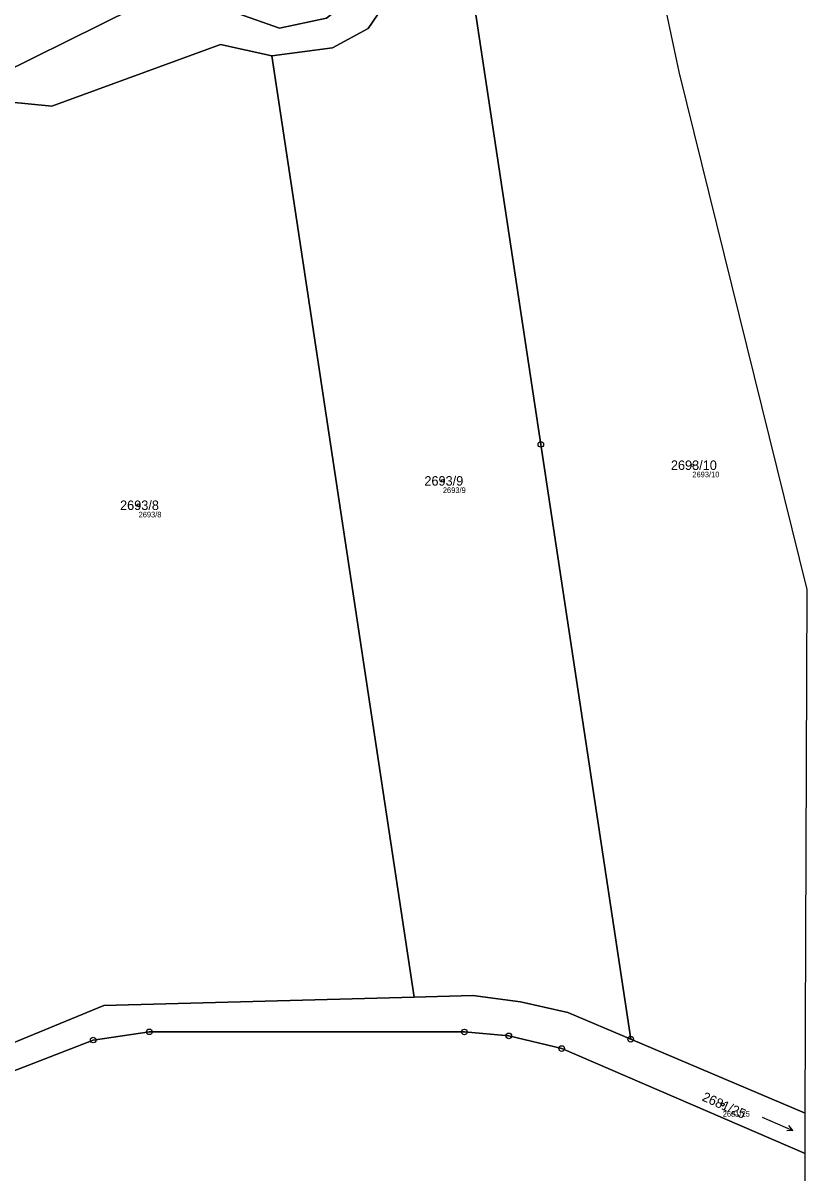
# Model space of a CAD drawing. Extents: x -758777 to -757896, y -1175225 to -1174486.
# Drawn here: x -758036.1 to -757895.9, y -1174952.5 to -1174746.8 of the extents above; entities that cross this region are included whole.
import ezdxf

# ---------------------------------------------------------------- set-up
doc = ezdxf.new("R2010")
doc.units = 0
for name, color, linetype in [('Definiční body', 7, 'Continuous'), ('Hranice parcel', 7, 'Continuous'), ('Parcelní čísla', 7, 'Continuous'), ('Polygon parcely', 7, 'Continuous'), ('Značky bodu BP', 7, 'Continuous'), ('Značky kultur', 7, 'Continuous')]:
    doc.layers.add(name, color=color, linetype=linetype)

msp = doc.modelspace()

# ---------------------------------------------------------------- linework, layer by layer
at = {"layer": 'Definiční body'}
for centre in [(-757916.44, -1174825.87), (-757961.06, -1174828.68), (-758015.47, -1174833.04), (-757911, -1174940.28)]:
    msp.add_circle(centre, 0.25, dxfattribs=at)
at = {"layer": 'Hranice parcel'}
for p, q in [((-757966.21, -1174921.06), (-757991.64, -1174752.6)), ((-757927.46, -1174928.58), (-757896.24, -1174941.82))]:
    msp.add_line(p, q, dxfattribs=at)
for points in [[(-757934.61, -1174680.85), (-757964.85, -1174709.42), (-757976.05, -1174741.17), (-757981.89, -1174745.86), (-757990.29, -1174747.68), (-757997.69, -1174745.08), (-758004.14, -1174738), (-758040.32, -1174755.99), (-758089.84, -1174768.68), (-758142.71, -1174770.26), (-758184.87, -1174772.83)], [(-757991.64, -1174752.6), (-757980.81, -1174751.2), (-757974.41, -1174747.76), (-757967.73, -1174737.89), (-757961.29, -1174718.5), (-757959.61, -1174715.65)], [(-757959.61, -1174715.65), (-757943.53, -1174822.15), (-757927.46, -1174928.58)], [(-757991.64, -1174752.6), (-758000.82, -1174750.62), (-758030.99, -1174761.66), (-758038.84, -1174760.87), (-758056.09, -1174765.35)], [(-757896.26, -1174949.04), (-757939.8, -1174930.25), (-757949.26, -1174927.98), (-757957.21, -1174927.28), (-758013.54, -1174927.25), (-758023.59, -1174928.73), (-758047.8, -1174938.11), (-758063.96, -1174936.81), (-758089.79, -1174931.96), (-758110.46, -1174923.41), (-758137.06, -1174918.45)], [(-758040.03, -1174930.09), (-758021.7, -1174922.52), (-757966.21, -1174921.06)], [(-757966.21, -1174921.06), (-757955.71, -1174920.78), (-757947.16, -1174921.89), (-757938.71, -1174923.81), (-757927.46, -1174928.58)]]:
    msp.add_lwpolyline(points, dxfattribs=at)
at = {"layer": 'Polygon parcely'}
msp.add_line((-757896.26, -1174949.04), (-757896.24, -1174941.82), dxfattribs=at)
for points in [[(-758267.96, -1174782.93), (-758224.96, -1174775.27), (-758184.87, -1174772.83), (-758142.71, -1174770.26), (-758089.84, -1174768.68), (-758040.32, -1174755.99), (-758004.14, -1174738), (-757997.69, -1174745.08), (-757990.29, -1174747.68), (-757981.89, -1174745.86), (-757976.05, -1174741.17), (-757964.85, -1174709.42), (-757934.61, -1174680.85)], [(-757932.38, -1174691.39), (-757939.6, -1174695.85), (-757955.61, -1174708.87), (-757959.61, -1174715.65), (-757943.53, -1174822.15), (-757927.46, -1174928.58), (-757896.24, -1174941.82)], [(-757896.24, -1174941.82), (-757895.94, -1174848.13), (-757918.79, -1174755.48), (-757932.38, -1174691.39)], [(-758004.14, -1174738), (-758040.32, -1174755.99), (-758089.84, -1174768.68), (-758142.71, -1174770.26), (-758184.87, -1174772.83), (-758184.92, -1174776.46), (-758157.99, -1174775.16), (-758156.63, -1174775.13), (-758141.37, -1174774.78), (-758125.97, -1174774.42), (-758112.36, -1174774.1), (-758087.64, -1174773.53), (-758083.84, -1174772.54), (-758056.09, -1174765.35), (-758038.84, -1174760.87), (-758030.99, -1174761.66), (-758000.82, -1174750.62), (-757991.64, -1174752.6), (-757980.81, -1174751.2), (-757974.41, -1174747.76), (-757967.73, -1174737.89)], [(-757981.89, -1174745.86), (-757990.29, -1174747.68), (-757997.69, -1174745.08)], [(-757896.24, -1174941.82), (-757927.46, -1174928.58), (-757938.71, -1174923.81), (-757947.16, -1174921.89), (-757955.71, -1174920.78), (-757966.21, -1174921.06), (-758021.7, -1174922.52), (-758040.03, -1174930.09)], [(-758047.8, -1174938.11), (-758023.59, -1174928.73), (-758013.54, -1174927.25), (-757957.21, -1174927.28), (-757949.26, -1174927.98), (-757939.8, -1174930.25), (-757896.26, -1174949.04)], [(-757896.26, -1174949.04), (-757939.8, -1174930.25), (-757949.26, -1174927.98), (-757957.21, -1174927.28), (-758013.54, -1174927.25), (-758023.59, -1174928.73), (-758047.8, -1174938.11)], [(-758264.85, -1175093.62), (-758230.82, -1175080.28), (-758125.25, -1175071.01), (-757896.3, -1174959.75), (-757896.26, -1174949.04)]]:
    msp.add_lwpolyline(points, dxfattribs=at)
for points in [[(-757927.46, -1174928.58), (-757943.53, -1174822.15), (-757959.61, -1174715.65), (-757961.29, -1174718.5), (-757967.73, -1174737.89), (-757974.41, -1174747.76), (-757980.81, -1174751.2), (-757991.64, -1174752.6), (-757966.21, -1174921.06), (-757955.71, -1174920.78), (-757947.16, -1174921.89), (-757938.71, -1174923.81)], [(-758000.82, -1174750.62), (-758030.99, -1174761.66), (-758038.84, -1174760.87), (-758056.09, -1174765.35), (-758040.03, -1174930.09), (-758021.7, -1174922.52), (-757966.21, -1174921.06), (-757991.64, -1174752.6)]]:
    msp.add_lwpolyline(points, close=True, dxfattribs=at)
at = {"layer": 'Značky bodu BP'}
for centre, radius in [((-757943.53, -1174822.15), 0.5), ((-757943.53, -1174822.15), 0.0303), ((-758013.54, -1174927.25), 0.5), ((-758013.54, -1174927.25), 0.0303), ((-757957.21, -1174927.28), 0.5), ((-757957.21, -1174927.28), 0.0303), ((-757949.26, -1174927.98), 0.5), ((-757949.26, -1174927.98), 0.0303), ((-757927.46, -1174928.58), 0.5), ((-758023.59, -1174928.73), 0.5), ((-758023.59, -1174928.73), 0.0303), ((-757939.8, -1174930.25), 0.5), ((-757939.8, -1174930.25), 0.0303), ((-757927.46, -1174928.58), 0.0303)]:
    msp.add_circle(centre, radius, dxfattribs=at)
at = {"layer": 'Značky kultur'}
for p, q in [((-757903.98, -1174942.53), (-757898.46, -1174944.88)), ((-757898.46, -1174944.88), (-757899.16, -1174944.03)), ((-757898.46, -1174944.88), (-757899.55, -1174944.96))]:
    msp.add_line(p, q, dxfattribs=at)

# ---------------------------------------------------------------- texts
at = {"layer": 'Definiční body'}
for s, p in [('2693/10', (-757916.44, -1174828.03)), ('2693/9', (-757961.06, -1174830.84)), ('2693/8', (-758015.47, -1174835.2)), ('2681/25', (-757911, -1174942.44))]:
    msp.add_text(s, height=1, dxfattribs=at).set_placement(p)
at = {"layer": 'Parcelní čísla'}
for s, p in [('2693/10', (-757920.28, -1174826.72)), ('2693/9', (-757964.36, -1174829.53)), ('2693/8', (-758018.78, -1174833.89))]:
    msp.add_text(s, height=1.7, dxfattribs=at).set_placement(p)
msp.add_text('2681/25', height=1.7, rotation=336, dxfattribs=at).set_placement((-757914.85, -1174939.5))

doc.saveas('drawing.dxf')
